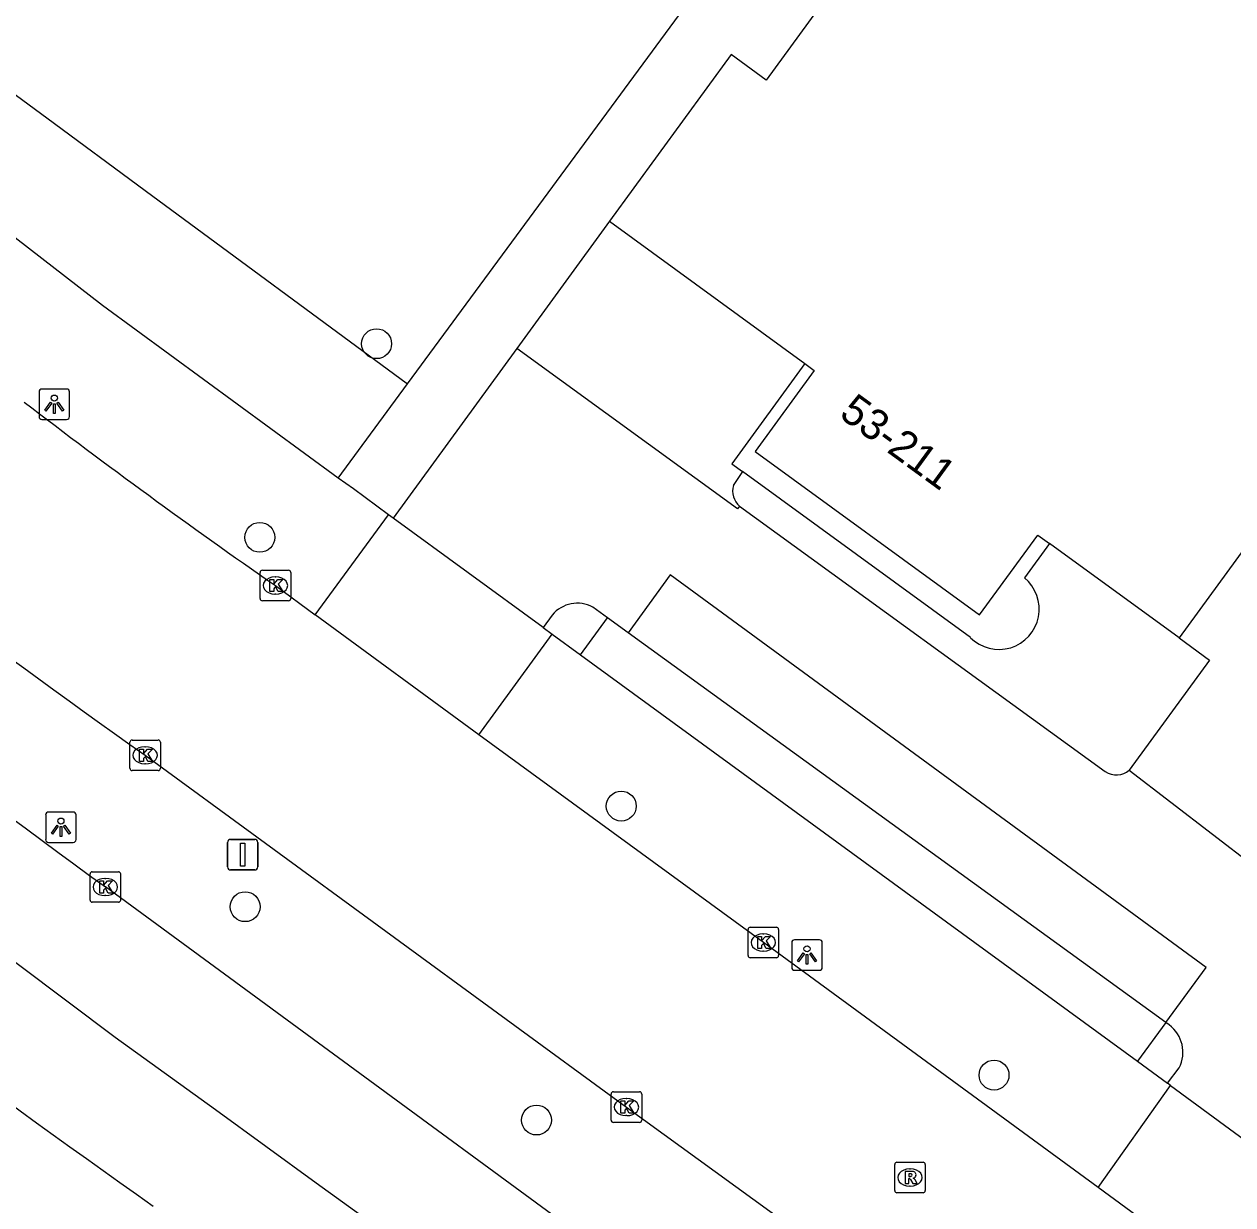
# Model space of a CAD drawing. Extents: x 159675 to 160530, y 382179 to 382901.
# Drawn here: x 159817.71 to 159857.22, y 382378.72 to 382417.34 of the extents above; entities that cross this region are included whole.
import ezdxf

# ---------------------------------------------------------------- set-up
doc = ezdxf.new("R2010")
doc.units = 0
for name, color, linetype in [('IMGEO_Boom', 7, 'Continuous'), ('IMGEO_Groenvoorziening', 7, 'Continuous'), ('IMGEO_Kolk', 7, 'Continuous'), ('IMGEO_Lichtpunt', 7, 'Continuous'), ('IMGEO_Loofbos', 7, 'Continuous'), ('IMGEO_Pand', 7, 'Continuous'), ('IMGEO_Pand_nummerreeks', 7, 'Continuous'), ('IMGEO_Parkeervlak_open', 7, 'Continuous'), ('IMGEO_Rijbaan_lokaal_open', 7, 'Continuous'), ('IMGEO_Rijbaan_regionaal_gesloten', 7, 'Continuous'), ('IMGEO_Rioolput', 7, 'Continuous'), ('IMGEO_Verkeersbordpaal', 7, 'Continuous'), ('IMGEO_Voetpad_open', 7, 'Continuous')]:
    doc.layers.add(name, color=color, linetype=linetype)

msp = doc.modelspace()

# ---------------------------------------------------------------- linework, layer by layer
at = {"layer": 'IMGEO_Boom'}
for centre in [(159829.228, 382406.887), (159825.411, 382400.554), (159837.227, 382391.765), (159824.931, 382388.474), (159849.412, 382382.968), (159834.456, 382381.497)]:
    msp.add_circle(centre, 0.489, dxfattribs=at)
at = {"layer": 'IMGEO_Groenvoorziening'}
msp.add_lwpolyline([(159827.974, 382402.485), (159830.242, 382405.57)], dxfattribs=at)
at = {"layer": 'IMGEO_Kolk'}
for p, q in [((159825.421, 382398.552), (159825.421, 382399.404)), ((159825.496, 382399.478), (159826.348, 382399.478)), ((159825.909, 382399.258), (159825.934, 382399.258)), ((159826.422, 382399.404), (159826.422, 382398.552)), ((159826.348, 382398.478), (159825.496, 382398.478)), ((159825.932, 382398.698), (159825.907, 382398.698)), ((159821.161, 382393), (159821.161, 382393.852)), ((159821.236, 382393.926), (159822.088, 382393.926)), ((159821.649, 382393.706), (159821.674, 382393.706)), ((159822.162, 382393.852), (159822.162, 382393)), ((159822.088, 382392.926), (159821.236, 382392.926)), ((159821.672, 382393.146), (159821.647, 382393.146)), ((159819.861, 382388.693), (159819.861, 382389.545)), ((159819.936, 382389.619), (159820.788, 382389.619)), ((159820.349, 382389.399), (159820.374, 382389.399)), ((159820.862, 382389.545), (159820.862, 382388.693)), ((159820.788, 382388.619), (159819.936, 382388.619)), ((159820.372, 382388.839), (159820.347, 382388.839)), ((159841.445, 382387.804), (159842.297, 382387.804)), ((159841.37, 382386.878), (159841.37, 382387.73)), ((159841.858, 382387.584), (159841.883, 382387.584)), ((159842.371, 382387.73), (159842.371, 382386.878)), ((159841.881, 382387.024), (159841.856, 382387.024)), ((159842.297, 382386.804), (159841.445, 382386.804)), ((159836.895, 382381.495), (159836.895, 382382.347)), ((159836.97, 382382.421), (159837.822, 382382.421)), ((159837.896, 382382.347), (159837.896, 382381.495)), ((159837.383, 382382.201), (159837.408, 382382.201)), ((159837.406, 382381.641), (159837.381, 382381.641)), ((159837.822, 382381.421), (159836.97, 382381.421))]:
    msp.add_line(p, q, dxfattribs=at)
for points in [[(159825.421, 382398.552), (159825.421, 382399.404)], [(159825.496, 382399.478), (159826.348, 382399.478)], [(159826.422, 382399.404), (159826.422, 382398.552)], [(159825.742, 382399.178), (159825.865, 382399.178), (159825.865, 382399.027), (159825.995, 382399.178), (159826.159, 382399.178), (159826.013, 382399.027), (159826.166, 382398.778), (159826.014, 382398.778), (159825.929, 382398.942), (159825.865, 382398.875), (159825.865, 382398.778), (159825.742, 382398.778), (159825.742, 382399.178)], [(159826.348, 382398.478), (159825.496, 382398.478)], [(159821.161, 382393), (159821.161, 382393.852)], [(159821.236, 382393.926), (159822.088, 382393.926)], [(159822.162, 382393.852), (159822.162, 382393)], [(159821.482, 382393.626), (159821.605, 382393.626), (159821.605, 382393.475), (159821.735, 382393.626), (159821.899, 382393.626), (159821.753, 382393.475), (159821.906, 382393.226), (159821.754, 382393.226), (159821.669, 382393.39), (159821.605, 382393.323), (159821.605, 382393.226), (159821.482, 382393.226), (159821.482, 382393.626)], [(159822.088, 382392.926), (159821.236, 382392.926)], [(159819.861, 382388.693), (159819.861, 382389.545)], [(159819.936, 382389.619), (159820.788, 382389.619)], [(159820.862, 382389.545), (159820.862, 382388.693)], [(159820.182, 382389.319), (159820.305, 382389.319), (159820.305, 382389.168), (159820.435, 382389.319), (159820.599, 382389.319), (159820.453, 382389.168), (159820.606, 382388.919), (159820.454, 382388.919), (159820.369, 382389.083), (159820.305, 382389.016), (159820.305, 382388.919), (159820.182, 382388.919), (159820.182, 382389.319)], [(159820.788, 382388.619), (159819.936, 382388.619)], [(159841.445, 382387.804), (159842.297, 382387.804)], [(159841.37, 382386.878), (159841.37, 382387.73)], [(159841.691, 382387.504), (159841.814, 382387.504), (159841.814, 382387.353), (159841.944, 382387.504), (159842.108, 382387.504), (159841.962, 382387.353), (159842.115, 382387.104), (159841.963, 382387.104), (159841.878, 382387.268), (159841.814, 382387.201), (159841.814, 382387.104), (159841.691, 382387.104), (159841.691, 382387.504)], [(159842.371, 382387.73), (159842.371, 382386.878)], [(159842.297, 382386.804), (159841.445, 382386.804)], [(159836.895, 382381.495), (159836.895, 382382.347)], [(159836.97, 382382.421), (159837.822, 382382.421)], [(159837.896, 382382.347), (159837.896, 382381.495)], [(159837.216, 382382.121), (159837.339, 382382.121), (159837.339, 382381.97), (159837.469, 382382.121), (159837.633, 382382.121), (159837.487, 382381.97), (159837.64, 382381.721), (159837.488, 382381.721), (159837.403, 382381.885), (159837.339, 382381.818), (159837.339, 382381.721), (159837.216, 382381.721), (159837.216, 382382.121)], [(159837.822, 382381.421), (159836.97, 382381.421)]]:
    msp.add_lwpolyline(points, dxfattribs=at)
for centre, start, end in [((159825.498, 382399.402), 91.552, 178.448), ((159825.498, 382399.402), 91.552, 178.448), ((159826.346, 382399.402), 1.552, 88.448), ((159826.346, 382399.402), 1.552, 88.448), ((159825.498, 382398.554), 181.552, 268.448), ((159825.498, 382398.554), 181.552, 268.448), ((159826.346, 382398.554), 271.552, 358.448), ((159826.346, 382398.554), 271.552, 358.448), ((159821.238, 382393.85), 91.552, 178.448), ((159821.238, 382393.85), 91.552, 178.448), ((159822.086, 382393.85), 1.552, 88.448), ((159822.086, 382393.85), 1.552, 88.448), ((159821.238, 382393.002), 181.552, 268.448), ((159821.238, 382393.002), 181.552, 268.448), ((159822.086, 382393.002), 271.552, 358.448), ((159822.086, 382393.002), 271.552, 358.448), ((159819.938, 382389.543), 91.552, 178.448), ((159819.938, 382389.543), 91.552, 178.448), ((159820.786, 382389.543), 1.552, 88.448), ((159820.786, 382389.543), 1.552, 88.448), ((159819.938, 382388.695), 181.552, 268.448), ((159819.938, 382388.695), 181.552, 268.448), ((159820.786, 382388.695), 271.552, 358.448), ((159820.786, 382388.695), 271.552, 358.448), ((159841.447, 382387.728), 91.552, 178.448), ((159841.447, 382387.728), 91.552, 178.448), ((159842.295, 382387.728), 1.552, 88.448), ((159842.295, 382387.728), 1.552, 88.448), ((159841.447, 382386.88), 181.552, 268.448), ((159841.447, 382386.88), 181.552, 268.448), ((159842.295, 382386.88), 271.552, 358.448), ((159842.295, 382386.88), 271.552, 358.448), ((159836.972, 382382.345), 91.552, 178.448), ((159836.972, 382382.345), 91.552, 178.448), ((159837.82, 382382.345), 1.552, 88.448), ((159837.82, 382382.345), 1.552, 88.448), ((159836.972, 382381.497), 181.552, 268.448), ((159836.972, 382381.497), 181.552, 268.448), ((159837.82, 382381.497), 271.552, 358.448), ((159837.82, 382381.497), 271.552, 358.448)]:
    msp.add_arc(centre, 0.0765, start, end, dxfattribs=at)
for centre, major_axis, ratio, start_param, end_param in [((159825.908, 382398.978), (-0.387, 0.002), 0.722429, 4.712389, 7.853982), ((159825.933, 382398.978), (-0.39, 0.002), 0.717154, 1.570796, 4.712389), ((159821.648, 382393.426), (-0.387, 0.002), 0.722429, 4.712389, 7.853982), ((159821.673, 382393.426), (-0.39, 0.002), 0.717154, 1.570796, 4.712389), ((159820.348, 382389.119), (-0.387, 0.002), 0.722429, 4.712389, 7.853982), ((159820.373, 382389.119), (-0.39, 0.002), 0.717154, 1.570796, 4.712389), ((159841.857, 382387.304), (-0.387, 0.002), 0.722429, 4.712389, 7.853982), ((159841.882, 382387.304), (-0.39, 0.002), 0.717154, 1.570796, 4.712389), ((159837.382, 382381.921), (-0.387, 0.002), 0.722429, 4.712389, 7.853982), ((159837.407, 382381.921), (-0.39, 0.002), 0.717154, 1.570796, 4.712389)]:
    msp.add_ellipse(centre, major_axis=major_axis, ratio=ratio, start_param=start_param, end_param=end_param, dxfattribs=at)
at = {"layer": 'IMGEO_Lichtpunt'}
for p, q in [((159818.194, 382405.309), (159818.194, 382404.502)), ((159818.194, 382405.309), (159818.194, 382404.502)), ((159819.096, 382405.404), (159818.288, 382405.404)), ((159819.096, 382405.404), (159818.288, 382405.404)), ((159819.19, 382404.502), (159819.19, 382405.309)), ((159819.19, 382404.502), (159819.19, 382405.309)), ((159818.288, 382404.408), (159819.096, 382404.408)), ((159818.288, 382404.408), (159819.096, 382404.408)), ((159818.411, 382391.476), (159818.411, 382390.669)), ((159818.411, 382391.476), (159818.411, 382390.669)), ((159819.313, 382391.571), (159818.505, 382391.571)), ((159819.313, 382391.571), (159818.505, 382391.571)), ((159819.407, 382390.669), (159819.407, 382391.476)), ((159819.407, 382390.669), (159819.407, 382391.476)), ((159818.505, 382390.575), (159819.313, 382390.575)), ((159818.505, 382390.575), (159819.313, 382390.575)), ((159843.702, 382387.393), (159842.894, 382387.393)), ((159843.702, 382387.393), (159842.894, 382387.393)), ((159842.8, 382387.298), (159842.8, 382386.491)), ((159842.8, 382387.298), (159842.8, 382386.491)), ((159843.796, 382386.491), (159843.796, 382387.298)), ((159843.796, 382386.491), (159843.796, 382387.298)), ((159842.894, 382386.397), (159843.702, 382386.397)), ((159842.894, 382386.397), (159843.702, 382386.397))]:
    msp.add_line(p, q, dxfattribs=at)
for points in [[(159818.568, 382404.973), (159818.607, 382404.945), (159818.419, 382404.683), (159818.381, 382404.71), (159818.568, 382404.973)], [(159818.67, 382404.925), (159818.717, 382404.925), (159818.717, 382404.603), (159818.67, 382404.603), (159818.67, 382404.925)], [(159818.78, 382404.945), (159818.818, 382404.972), (159819.005, 382404.71), (159818.966, 382404.682), (159818.78, 382404.945)], [(159818.785, 382391.14), (159818.824, 382391.112), (159818.636, 382390.85), (159818.598, 382390.877), (159818.785, 382391.14)], [(159818.887, 382391.092), (159818.934, 382391.092), (159818.934, 382390.77), (159818.887, 382390.77), (159818.887, 382391.092)], [(159818.997, 382391.112), (159819.035, 382391.139), (159819.222, 382390.877), (159819.183, 382390.849), (159818.997, 382391.112)], [(159843.174, 382386.962), (159843.213, 382386.934), (159843.025, 382386.672), (159842.987, 382386.699), (159843.174, 382386.962)], [(159843.276, 382386.914), (159843.323, 382386.914), (159843.323, 382386.592), (159843.276, 382386.592), (159843.276, 382386.914)], [(159843.386, 382386.934), (159843.424, 382386.961), (159843.611, 382386.699), (159843.572, 382386.671), (159843.386, 382386.934)]]:
    msp.add_lwpolyline(points, dxfattribs=at)
for centre in [(159818.693, 382405.107), (159818.91, 382391.274), (159843.299, 382387.096)]:
    msp.add_circle(centre, 0.0994, dxfattribs=at)
for centre, start, end in [((159818.288, 382405.309), 90, 180), ((159818.288, 382405.309), 90, 180), ((159819.096, 382405.309), 0, 90), ((159819.096, 382405.309), 0, 90), ((159818.288, 382404.502), 180, 270), ((159818.288, 382404.502), 180, 270), ((159819.096, 382404.502), 270, 0), ((159819.096, 382404.502), 270, 360), ((159818.505, 382391.476), 90, 180), ((159818.505, 382391.476), 90, 180), ((159819.313, 382391.476), 0, 90), ((159819.313, 382391.476), 0, 90), ((159818.505, 382390.669), 180, 270), ((159818.505, 382390.669), 180, 270), ((159819.313, 382390.669), 270, 0), ((159819.313, 382390.669), 270, 360), ((159842.894, 382387.298), 90, 180), ((159842.894, 382387.298), 90, 180), ((159843.702, 382387.298), 0, 90), ((159843.702, 382387.298), 0, 90), ((159842.894, 382386.491), 180, 270), ((159842.894, 382386.491), 180, 270), ((159843.702, 382386.491), 270, 0), ((159843.702, 382386.491), 270, 360)]:
    msp.add_arc(centre, 0.0946, start, end, dxfattribs=at)
at = {"layer": 'IMGEO_Loofbos'}
for points in [[(159795.303, 382442.693), (159791.814, 382436.688), (159800.943, 382428.659), (159811.368, 382419.491), (159818.446, 382414.27), (159821.663, 382411.898), (159830.242, 382405.57)], [(159830.242, 382405.57), (159844.306, 382424.692)]]:
    msp.add_lwpolyline(points, dxfattribs=at)
at = {"layer": 'IMGEO_Pand'}
for points in [[(159852.596, 382432.305), (159848.535, 382426.737), (159849.589, 382425.968), (159841.96, 382415.507), (159840.818, 382416.34), (159836.843, 382410.89)], [(159836.843, 382410.89), (159843.227, 382406.234)], [(159843.227, 382406.234), (159843.532, 382406.011), (159841.602, 382403.365), (159848.938, 382398.015), (159850.846, 382400.63), (159851.228, 382400.352)], [(159860.298, 382405.99), (159858.555, 382403.6), (159859.552, 382402.873), (159855.462, 382397.264)], [(159855.462, 382397.264), (159851.228, 382400.352)]]:
    msp.add_lwpolyline(points, dxfattribs=at)
at = {"layer": 'IMGEO_Parkeervlak_open'}
for points in [[(159836.843, 382410.89), (159833.812, 382406.727)], [(159855.03, 382384.685), (159837.457, 382397.431)]]:
    msp.add_lwpolyline(points, dxfattribs=at)
at = {"layer": 'IMGEO_Rijbaan_lokaal_open'}
for points in [[(159853.834, 382392.94), (159857.921, 382389.804), (159870.802, 382407.636), (159877.131, 382416.399), (159872.754, 382419.56)], [(159833.812, 382406.727), (159829.772, 382401.177)], [(159841.09, 382401.57), (159841.031, 382401.489), (159833.812, 382406.727)], [(159841.09, 382401.57), (159853.05, 382392.893)], [(159834.672, 382397.603), (159829.772, 382401.177)], [(159855.03, 382384.685), (159856.343, 382386.484), (159852.103, 382389.593), (159838.83, 382399.324), (159837.457, 382397.431)], [(159825.921, 382398.977), (159827.221, 382398.024)], [(159836.782, 382397.921), (159836.299, 382398.271)], [(159832.567, 382394.095), (159827.221, 382398.024)], [(159834.972, 382398.013), (159834.672, 382397.603)], [(159837.457, 382397.431), (159836.782, 382397.921)], [(159852.819, 382379.291), (159841.871, 382387.303), (159832.567, 382394.095)], [(159821.663, 382393.428), (159837.398, 382381.921), (159853.244, 382370.412), (159861.603, 382364.191), (159861.935, 382363.943), (159862.453, 382363.558), (159865.165, 382361.587), (159865.527, 382361.323), (159868.85, 382358.908), (159886.281, 382346.283), (159890.778, 382342.957), (159892.752, 382341.534), (159901.276, 382335.387), (159917.12, 382323.888), (159932.887, 382312.381), (159948.694, 382300.897), (159964.493, 382289.401), (159978.692, 382279.072), (159993.641, 382268.144), (159998.978, 382264.261)], [(159855.139, 382384.606), (159855.03, 382384.685)], [(159855.086, 382382.703), (159855.462, 382383.204)], [(159855.186, 382382.63), (159855.086, 382382.703)], [(159855.186, 382382.63), (159860.432, 382378.766)], [(159858.078, 382375.421), (159852.819, 382379.291)]]:
    msp.add_lwpolyline(points, dxfattribs=at)
for centre, radius, start, end in [((159963.031, 382594.312), 245.64, 230.30196, 234.86487), ((159948.559, 382575.441), 214.895, 232.48935, 235.20163), ((159835.793, 382397.332), 1.067, 61.6759, 140.3289), ((159853.411, 382393.432), 0.649, 236.1974, 310.664), ((159854.484, 382383.717), 1.104, 332.332, 53.6154)]:
    msp.add_arc(centre, radius, start, end, dxfattribs=at)
at = {"layer": 'IMGEO_Rijbaan_regionaal_gesloten'}
for points in [[(159814.303, 382388.992), (159820.684, 382384.211), (159823.962, 382381.843), (159827.249, 382379.442), (159830.495, 382377.097), (159837.704, 382371.808), (159844.157, 382367.109), (159852.329, 382361.157), (159856.095, 382358.415), (159857.266, 382357.562), (159859.52, 382355.92), (159860.502, 382355.205), (159860.875, 382354.934), (159886.072, 382336.683), (159888.268, 382335.072), (159909.562, 382319.459), (159925.525, 382308.023), (159950.27, 382289.892), (159973.901, 382272.669)], [(159996.559, 382260.85), (159949.37, 382295.571), (159899.278, 382331.94), (159890.517, 382338.312), (159864.219, 382357.439), (159863.22, 382358.155), (159862.851, 382358.42), (159859.599, 382360.751), (159859.265, 382360.99), (159843.591, 382372.074), (159820.362, 382389.119)]]:
    msp.add_lwpolyline(points, dxfattribs=at)
for centre, radius, start, end in [((160053.044, 382708.523), 395.171, 230.95383, 233.92705), ((160055.936, 382709.342), 405.09, 231.68362, 234.71251)]:
    msp.add_arc(centre, radius, start, end, dxfattribs=at)
at = {"layer": 'IMGEO_Rioolput'}
for p, q in [((159846.165, 382379.192), (159846.165, 382380.044)), ((159846.24, 382380.118), (159847.092, 382380.118)), ((159846.653, 382379.898), (159846.678, 382379.898)), ((159847.166, 382380.044), (159847.166, 382379.192)), ((159847.092, 382379.118), (159846.24, 382379.118)), ((159846.676, 382379.338), (159846.651, 382379.338))]:
    msp.add_line(p, q, dxfattribs=at)
for points in [[(159846.165, 382379.192), (159846.165, 382380.044)], [(159846.24, 382380.118), (159847.092, 382380.118)], [(159847.166, 382380.044), (159847.166, 382379.192)], [(159846.754, 382379.816), (159846.502, 382379.818), (159846.502, 382379.418)], [(159846.502, 382379.418), (159846.626, 382379.418), (159846.626, 382379.58), (159846.637, 382379.58)], [(159846.68, 382379.737), (159846.626, 382379.737), (159846.626, 382379.656)], [(159846.626, 382379.656), (159846.678, 382379.656)], [(159846.684, 382379.551), (159846.755, 382379.418), (159846.895, 382379.418), (159846.83, 382379.544)], [(159847.092, 382379.118), (159846.24, 382379.118)]]:
    msp.add_lwpolyline(points, dxfattribs=at)
for centre, radius, start, end in [((159846.242, 382380.042), 0.0765, 91.552, 178.448), ((159846.242, 382380.042), 0.0765, 91.552, 178.448), ((159847.09, 382380.042), 0.0765, 1.552, 88.448), ((159847.09, 382380.042), 0.0765, 1.552, 88.448), ((159846.636, 382379.527), 0.0533, 26.0293, 88.6989), ((159846.662, 382379.845), 0.19, 274.7715, 282.9687), ((159846.686, 382379.641), 0.0964, 77.0061, 93.1865), ((159846.7, 382379.698), 0.0378, 276.6634, 79.6772), ((159846.753, 382379.706), 0.109, 350.3612, 89.416), ((159846.751, 382379.706), 0.112, 277.5842, 350.9817), ((159846.735, 382379.491), 0.108, 29.5134, 73.7905), ((159846.242, 382379.194), 0.0765, 181.552, 268.448), ((159846.242, 382379.194), 0.0765, 181.552, 268.448), ((159847.09, 382379.194), 0.0765, 271.552, 358.448), ((159847.09, 382379.194), 0.0765, 271.552, 358.448)]:
    msp.add_arc(centre, radius, start, end, dxfattribs=at)
for centre, major_axis, ratio, start_param, end_param in [((159846.652, 382379.618), (-0.387, 0.002), 0.722429, 4.712389, 7.853982), ((159846.677, 382379.618), (-0.39, 0.002), 0.717154, 1.570796, 4.712389)]:
    msp.add_ellipse(centre, major_axis=major_axis, ratio=ratio, start_param=start_param, end_param=end_param, dxfattribs=at)
at = {"layer": 'IMGEO_Verkeersbordpaal'}
for p, q in [((159824.356, 382389.776), (159824.356, 382390.576)), ((159824.356, 382390.576), (159824.356, 382389.776)), ((159824.456, 382390.676), (159825.246, 382390.676)), ((159825.246, 382390.676), (159824.456, 382390.676)), ((159825.346, 382390.576), (159825.346, 382389.776)), ((159825.346, 382389.776), (159825.346, 382390.576)), ((159825.246, 382389.676), (159824.456, 382389.676)), ((159824.456, 382389.676), (159825.246, 382389.676))]:
    msp.add_line(p, q, dxfattribs=at)
msp.add_lwpolyline([(159824.776, 382390.551), (159824.926, 382390.551), (159824.926, 382389.801), (159824.776, 382389.801), (159824.776, 382390.551)], dxfattribs=at)
for centre, start, end in [((159824.456, 382390.576), 90, 180), ((159824.456, 382390.576), 90, 180), ((159825.246, 382390.576), 0, 90), ((159825.246, 382390.576), 360, 90), ((159824.456, 382389.776), 180, 270), ((159824.456, 382389.776), 180, 270), ((159825.246, 382389.776), 270, 0), ((159825.246, 382389.776), 270, 0)]:
    msp.add_arc(centre, 0.1, start, end, dxfattribs=at)
at = {"layer": 'IMGEO_Voetpad_open'}
for points in [[(159827.974, 382402.485), (159820.265, 382408.131), (159817.078, 382410.61), (159812.216, 382414.568)], [(159843.227, 382406.234), (159840.841, 382402.963), (159841.185, 382402.712)], [(159829.622, 382401.286), (159828.473, 382402.136), (159828.223, 382402.31), (159827.974, 382402.485)], [(159841.185, 382402.712), (159840.89, 382402.252)], [(159848.639, 382397.273), (159841.185, 382402.712)], [(159827.221, 382398.024), (159829.622, 382401.286)], [(159829.772, 382401.177), (159829.622, 382401.286)], [(159851.228, 382400.352), (159850.403, 382399.229)], [(159835.897, 382396.709), (159836.782, 382397.921)], [(159832.567, 382394.095), (159834.968, 382397.387)], [(159834.672, 382397.603), (159834.968, 382397.387)], [(159834.968, 382397.387), (159835.897, 382396.709)], [(159855.462, 382397.264), (159856.458, 382396.538), (159853.834, 382392.94)], [(159835.897, 382396.709), (159854.105, 382383.419)], [(159855.03, 382384.685), (159854.105, 382383.419)], [(159854.105, 382383.419), (159855.086, 382382.703)], [(159852.819, 382379.291), (159855.186, 382382.63)]]:
    msp.add_lwpolyline(points, dxfattribs=at)
for centre, radius, start, end in [((159841.558, 382402.078), 0.69, 165.3689, 227.3192), ((159849.571, 382398.206), 1.319, 225.0431, 50.866)]:
    msp.add_arc(centre, radius, start, end, dxfattribs=at)

# ---------------------------------------------------------------- texts
at = {"layer": 'IMGEO_Pand_nummerreeks'}
msp.add_text('53-211', height=1, rotation=323.8979, dxfattribs=at).set_placement((159844.312, 382404.507))

doc.saveas('drawing.dxf')
